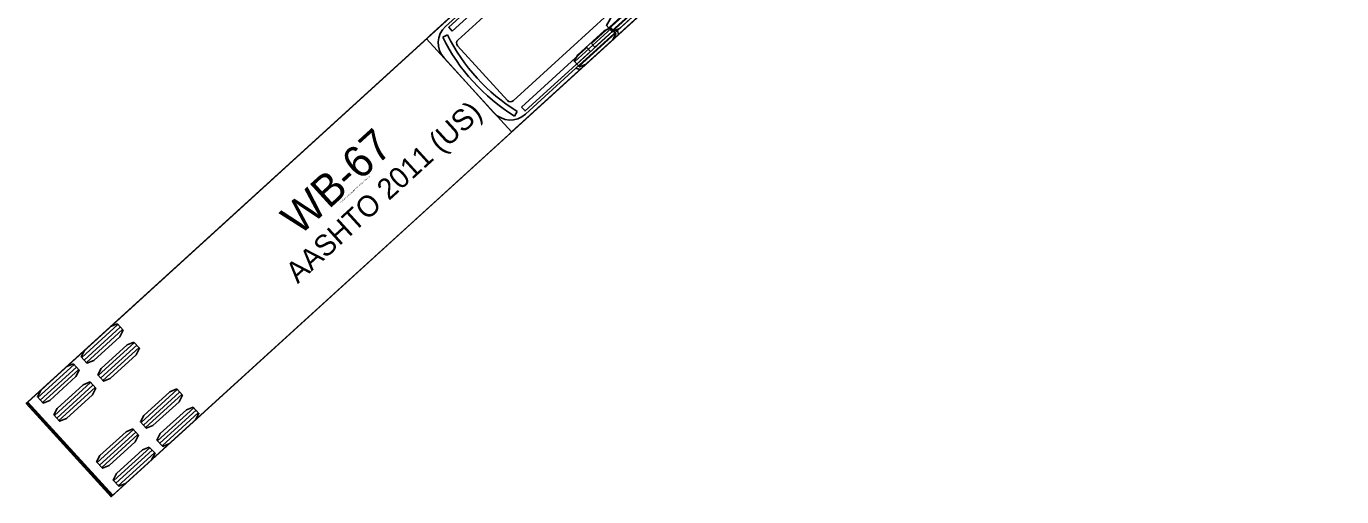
# Model space of a CAD drawing. Extents: x 1639988 to 1641860, y 841974 to 844187.
# Drawn here: x 1639988.4 to 1640077.1, y 843375.5 to 843407.2 of the extents above; entities that cross this region are included whole.
import ezdxf

# ---------------------------------------------------------------- set-up
doc = ezdxf.new("R2010")
doc.units = 0
for name, color, linetype in [('Scratch_Level_1', 7, 'Continuous'), ('Scratch_Level_3', 7, 'Continuous'), ('Scratch_Level_4', 7, 'Continuous'), ('Scratch_Level_5', 7, 'Continuous'), ('Scratch_Level_6', 7, 'Continuous')]:
    doc.layers.add(name, color=color, linetype=linetype)

msp = doc.modelspace()

# ---------------------------------------------------------------- linework, layer by layer
at = {"layer": 'Scratch_Level_1'}
for p, q in [((1640030.453, 843409.562), (1640027.743, 843407.093)), ((1640030.608, 843409.393), (1640027.897, 843406.923)), ((1639994.621, 843387.147), (1639992.182, 843384.925)), ((1639994.776, 843386.978), (1639992.336, 843384.755)), ((1639994.93, 843386.808), (1639992.49, 843384.586)), ((1639995.732, 843385.927), (1639993.293, 843383.705)), ((1639995.887, 843385.758), (1639993.447, 843383.535)), ((1639996.041, 843385.589), (1639993.602, 843383.366)), ((1639991.664, 843384.453), (1639989.225, 843382.231)), ((1639991.819, 843384.284), (1639989.379, 843382.061)), ((1639991.973, 843384.114), (1639989.534, 843381.892)), ((1639992.776, 843383.233), (1639990.336, 843381.011)), ((1639992.93, 843383.064), (1639990.49, 843380.842)), ((1639993.084, 843382.895), (1639990.645, 843380.672)), ((1639998.617, 843382.761), (1639996.178, 843380.539)), ((1639998.771, 843382.592), (1639996.332, 843380.369)), ((1639998.926, 843382.422), (1639996.486, 843380.2)), ((1639994.271, 843375.639), (1639988.547, 843381.923)), ((1639999.728, 843381.541), (1639997.289, 843379.319)), ((1639999.883, 843381.372), (1639997.443, 843379.149)), ((1640000.037, 843381.203), (1639997.598, 843378.98)), ((1639995.66, 843380.067), (1639993.221, 843377.845)), ((1639995.815, 843379.898), (1639993.375, 843377.675)), ((1639995.969, 843379.728), (1639993.53, 843377.506)), ((1639991.178, 843378.93), (1639990.999, 843379.126)), ((1639991.357, 843378.734), (1639991.409, 843378.781)), ((1639996.772, 843378.847), (1639994.332, 843376.625)), ((1639991.714, 843378.341), (1639991.536, 843378.537)), ((1639996.926, 843378.678), (1639994.486, 843376.456)), ((1639997.08, 843378.509), (1639994.641, 843376.286))]:
    msp.add_line(p, q, dxfattribs=at)
for points in [[(1639988.552, 843381.927), (1640075.48, 843461.123), (1640079.453, 843464.719), (1640083.447, 843468.294), (1640087.471, 843471.841), (1640091.525, 843475.35), (1640093.544, 843477.118), (1640095.576, 843478.872), (1640099.681, 843482.333), (1640103.837, 843485.735), (1640108.041, 843489.076), (1640112.291, 843492.356), (1640116.585, 843495.576), (1640120.921, 843498.735), (1640125.299, 843501.833), (1640129.717, 843504.87), (1640134.175, 843507.846), (1640138.671, 843510.76)], [(1640137.628, 843497.624), (1640133.283, 843494.579), (1640128.957, 843491.512), (1640124.652, 843488.422), (1640120.37, 843485.306), (1640116.113, 843482.163), (1640111.883, 843478.991), (1640107.682, 843475.786), (1640103.511, 843472.549), (1640099.37, 843469.276), (1640095.259, 843465.968), (1640091.175, 843462.622), (1640087.115, 843459.239), (1640083.077, 843455.821), (1640079.06, 843452.372), (1640075.061, 843448.895), (1640071.078, 843445.391), (1640067.108, 843441.865), (1640059.196, 843434.757), (1640051.304, 843427.597), (1639994.167, 843375.544), (1639988.442, 843381.828), (1639988.552, 843381.927), (1639988.552, 843381.927)], [(1639994.204, 843375.608), (1639994.218, 843375.592), (1639994.271, 843375.64), (1639998.46, 843379.456), (1640033.345, 843411.238), (1640030.483, 843414.38), (1640027.62, 843417.522), (1639992.736, 843385.739), (1639988.547, 843381.922), (1639988.495, 843381.875), (1639988.51, 843381.859)], [(1639988.526, 843381.841), (1639988.526, 843381.84), (1639990.975, 843379.153), (1639990.999, 843379.126), (1639990.947, 843379.079), (1639990.948, 843379.078), (1639991.128, 843378.88)], [(1639991.182, 843378.925), (1639991.533, 843378.539)], [(1639991.482, 843378.492), (1639991.661, 843378.294), (1639991.663, 843378.294), (1639991.714, 843378.341), (1639991.739, 843378.314), (1639994.187, 843375.627), (1639994.188, 843375.626)]]:
    msp.add_lwpolyline(points, dxfattribs=at)
for points in [[(1640030.261, 843409.773), (1640030.646, 843409.351), (1640030.382, 843408.878), (1640028.431, 843407.1), (1640027.935, 843406.881), (1640027.55, 843407.304), (1640027.814, 843407.777), (1640029.765, 843409.555)], [(1639994.583, 843387.189), (1639994.968, 843386.766), (1639994.743, 843386.328), (1639992.986, 843384.728), (1639992.529, 843384.544), (1639992.143, 843384.967), (1639992.369, 843385.405), (1639994.125, 843387.005)], [(1639995.694, 843385.969), (1639996.079, 843385.547), (1639995.854, 843385.108), (1639994.098, 843383.508), (1639993.64, 843383.324), (1639993.255, 843383.747), (1639993.48, 843384.185), (1639995.237, 843385.786)], [(1639991.626, 843384.495), (1639992.011, 843384.072), (1639991.786, 843383.634), (1639990.029, 843382.034), (1639989.572, 843381.85), (1639989.187, 843382.273), (1639989.412, 843382.711), (1639991.168, 843384.311)], [(1639992.737, 843383.275), (1639993.123, 843382.853), (1639992.897, 843382.414), (1639991.141, 843380.814), (1639990.683, 843380.63), (1639990.298, 843381.053), (1639990.523, 843381.492), (1639992.28, 843383.092)], [(1639998.579, 843382.803), (1639998.964, 843382.38), (1639998.739, 843381.942), (1639996.982, 843380.342), (1639996.525, 843380.158), (1639996.139, 843380.581), (1639996.365, 843381.019), (1639998.121, 843382.619)], [(1639999.69, 843381.583), (1640000.075, 843381.161), (1639999.85, 843380.722), (1639998.093, 843379.122), (1639997.636, 843378.938), (1639997.251, 843379.361), (1639997.476, 843379.799), (1639999.232, 843381.4)], [(1639995.622, 843380.109), (1639996.007, 843379.686), (1639995.782, 843379.248), (1639994.025, 843377.648), (1639993.568, 843377.464), (1639993.183, 843377.887), (1639993.408, 843378.325), (1639995.164, 843379.925)], [(1639996.733, 843378.889), (1639997.118, 843378.467), (1639996.893, 843378.028), (1639995.137, 843376.428), (1639994.679, 843376.244), (1639994.294, 843376.667), (1639994.519, 843377.106), (1639996.276, 843378.706)]]:
    msp.add_lwpolyline(points, close=True, dxfattribs=at)
for centre in [(1639988.492, 843381.827), (1639994.171, 843375.594)]:
    msp.add_circle(centre, 0.0266, dxfattribs=at)
for centre, radius, start, end in [((1639988.492, 843381.827), 0.0363, 61.41319, 22.57454), ((1639991.153, 843378.905), 0.0353, 45.67193, 224.02158), ((1639991.154, 843378.904), 0.0352, 222.36102, 41.36143), ((1639991.508, 843378.515), 0.0352, 43.31007, 222.31048), ((1639991.508, 843378.515), 0.0354, 226.62728, 38.81275), ((1639992.709, 843374.247), 2.022, 42.33575, 43.01951)]:
    msp.add_arc(centre, radius, start, end, dxfattribs=at)
at = {"layer": 'Scratch_Level_3'}
for p, q in [((1640030.453, 843409.562), (1640027.743, 843407.093)), ((1640030.608, 843409.393), (1640027.897, 843406.923)), ((1639994.621, 843387.147), (1639992.182, 843384.925)), ((1639994.776, 843386.978), (1639992.336, 843384.755)), ((1639994.93, 843386.808), (1639992.49, 843384.586)), ((1639995.732, 843385.927), (1639993.293, 843383.705)), ((1639995.887, 843385.758), (1639993.447, 843383.535)), ((1639996.041, 843385.589), (1639993.602, 843383.366)), ((1639991.664, 843384.453), (1639989.225, 843382.231)), ((1639991.819, 843384.284), (1639989.379, 843382.061)), ((1639991.973, 843384.114), (1639989.534, 843381.892)), ((1639992.776, 843383.233), (1639990.336, 843381.011)), ((1639992.93, 843383.064), (1639990.49, 843380.842)), ((1639993.084, 843382.895), (1639990.645, 843380.672)), ((1639998.617, 843382.761), (1639996.178, 843380.539)), ((1639998.771, 843382.592), (1639996.332, 843380.369)), ((1639998.926, 843382.422), (1639996.486, 843380.2)), ((1639994.271, 843375.639), (1639988.547, 843381.923)), ((1639999.728, 843381.541), (1639997.289, 843379.319)), ((1639999.883, 843381.372), (1639997.443, 843379.149)), ((1640000.037, 843381.203), (1639997.598, 843378.98)), ((1639995.66, 843380.067), (1639993.221, 843377.845)), ((1639995.815, 843379.898), (1639993.375, 843377.675)), ((1639995.969, 843379.728), (1639993.53, 843377.506)), ((1639991.178, 843378.93), (1639990.999, 843379.126)), ((1639991.357, 843378.734), (1639991.409, 843378.781)), ((1639996.772, 843378.847), (1639994.332, 843376.625)), ((1639991.714, 843378.341), (1639991.536, 843378.537)), ((1639996.926, 843378.678), (1639994.486, 843376.456)), ((1639997.08, 843378.509), (1639994.641, 843376.286))]:
    msp.add_line(p, q, dxfattribs=at)
for points in [[(1639988.549, 843381.924), (1640075.534, 843461.172), (1640079.512, 843464.772), (1640083.513, 843468.352), (1640087.542, 843471.903), (1640091.604, 843475.42), (1640093.625, 843477.189), (1640095.658, 843478.942), (1640099.765, 843482.403), (1640103.924, 843485.805), (1640108.132, 843489.147), (1640112.386, 843492.429), (1640116.685, 843495.651), (1640121.027, 843498.812), (1640125.411, 843501.911), (1640129.834, 843504.95), (1640134.297, 843507.926), (1640138.798, 843510.841)], [(1640138.602, 843498.073), (1640134.234, 843495.066), (1640129.887, 843492.035), (1640125.564, 843488.978), (1640121.266, 843485.892), (1640116.996, 843482.774), (1640112.756, 843479.624), (1640108.547, 843476.438), (1640104.369, 843473.216), (1640100.224, 843469.955), (1640096.105, 843466.653), (1640092.009, 843463.31), (1640087.938, 843459.929), (1640083.891, 843456.514), (1640079.864, 843453.066), (1640075.856, 843449.59), (1640071.865, 843446.086), (1640067.887, 843442.559), (1640059.961, 843435.448), (1640052.057, 843428.282), (1639994.167, 843375.544), (1639988.442, 843381.828), (1639988.549, 843381.924), (1639988.549, 843381.924)], [(1639994.204, 843375.608), (1639994.218, 843375.592), (1639994.271, 843375.64), (1639998.46, 843379.456), (1640033.345, 843411.238), (1640030.483, 843414.38), (1640027.62, 843417.522), (1639992.736, 843385.739), (1639988.547, 843381.922), (1639988.495, 843381.875), (1639988.51, 843381.859)], [(1639988.526, 843381.841), (1639988.526, 843381.84), (1639990.975, 843379.153), (1639990.999, 843379.126), (1639990.947, 843379.079), (1639990.948, 843379.078), (1639991.128, 843378.88)], [(1639991.182, 843378.925), (1639991.533, 843378.539)], [(1639991.482, 843378.492), (1639991.661, 843378.294), (1639991.663, 843378.294), (1639991.714, 843378.341), (1639991.739, 843378.314), (1639994.187, 843375.627), (1639994.188, 843375.626)]]:
    msp.add_lwpolyline(points, dxfattribs=at)
for points in [[(1640030.261, 843409.773), (1640030.646, 843409.351), (1640030.382, 843408.878), (1640028.431, 843407.1), (1640027.935, 843406.881), (1640027.55, 843407.304), (1640027.814, 843407.777), (1640029.765, 843409.555)], [(1639994.583, 843387.189), (1639994.968, 843386.766), (1639994.743, 843386.328), (1639992.986, 843384.728), (1639992.529, 843384.544), (1639992.143, 843384.967), (1639992.369, 843385.405), (1639994.125, 843387.005)], [(1639995.694, 843385.969), (1639996.079, 843385.547), (1639995.854, 843385.108), (1639994.098, 843383.508), (1639993.64, 843383.324), (1639993.255, 843383.747), (1639993.48, 843384.185), (1639995.237, 843385.786)], [(1639991.626, 843384.495), (1639992.011, 843384.072), (1639991.786, 843383.634), (1639990.029, 843382.034), (1639989.572, 843381.85), (1639989.187, 843382.273), (1639989.412, 843382.711), (1639991.168, 843384.311)], [(1639992.737, 843383.275), (1639993.123, 843382.853), (1639992.897, 843382.414), (1639991.141, 843380.814), (1639990.683, 843380.63), (1639990.298, 843381.053), (1639990.523, 843381.492), (1639992.28, 843383.092)], [(1639998.579, 843382.803), (1639998.964, 843382.38), (1639998.739, 843381.942), (1639996.982, 843380.342), (1639996.525, 843380.158), (1639996.139, 843380.581), (1639996.365, 843381.019), (1639998.121, 843382.619)], [(1639999.69, 843381.583), (1640000.075, 843381.161), (1639999.85, 843380.722), (1639998.093, 843379.122), (1639997.636, 843378.938), (1639997.251, 843379.361), (1639997.476, 843379.799), (1639999.232, 843381.4)], [(1639995.622, 843380.109), (1639996.007, 843379.686), (1639995.782, 843379.248), (1639994.025, 843377.648), (1639993.568, 843377.464), (1639993.183, 843377.887), (1639993.408, 843378.325), (1639995.164, 843379.925)], [(1639996.733, 843378.889), (1639997.118, 843378.467), (1639996.893, 843378.028), (1639995.137, 843376.428), (1639994.679, 843376.244), (1639994.294, 843376.667), (1639994.519, 843377.106), (1639996.276, 843378.706)]]:
    msp.add_lwpolyline(points, close=True, dxfattribs=at)
for centre in [(1639988.492, 843381.827), (1639994.171, 843375.594)]:
    msp.add_circle(centre, 0.0266, dxfattribs=at)
for centre, radius, start, end in [((1639988.492, 843381.827), 0.0363, 61.41319, 22.57454), ((1639991.153, 843378.905), 0.0353, 45.67193, 224.02158), ((1639991.154, 843378.904), 0.0352, 222.36102, 41.36143), ((1639991.508, 843378.515), 0.0352, 43.31007, 222.31048), ((1639991.508, 843378.515), 0.0354, 226.62728, 38.81275), ((1639992.709, 843374.247), 2.022, 42.33575, 43.01951)]:
    msp.add_arc(centre, radius, start, end, dxfattribs=at)
at = {"layer": 'Scratch_Level_4'}
for p, q in [((1640044.461, 843430.861), (1640017.53, 843406.325)), ((1640021.259, 843402.231), (1640048.19, 843426.767)), ((1640027.873, 843407.098), (1640025.409, 843404.853)), ((1640028.292, 843406.975), (1640025.493, 843404.425)), ((1640028.013, 843406.944), (1640025.549, 843404.699)), ((1640028.153, 843406.79), (1640025.689, 843404.545)), ((1640017.512, 843405.943), (1640020.878, 843402.249))]:
    msp.add_line(p, q, dxfattribs=at)
for points in [[(1640015.629, 843406.597), (1640063.06, 843449.817), (1640070.951, 843457.031), (1640078.888, 843464.23), (1640090.806, 843475.083), (1640092.811, 843476.877), (1640094.833, 843478.655), (1640096.869, 843480.416), (1640098.92, 843482.162), (1640100.985, 843483.892), (1640103.064, 843485.606), (1640105.157, 843487.304), (1640107.263, 843488.987), (1640111.513, 843492.306), (1640115.812, 843495.563), (1640120.156, 843498.756), (1640124.538, 843501.882), (1640128.957, 843504.942), (1640133.413, 843507.935), (1640137.905, 843510.864)], [(1640139.344, 843500.335), (1640134.956, 843497.359), (1640130.598, 843494.356), (1640126.277, 843491.318), (1640121.995, 843488.234), (1640117.753, 843485.098), (1640113.548, 843481.908), (1640109.381, 843478.668), (1640105.25, 843475.378), (1640101.155, 843472.039), (1640097.092, 843468.655), (1640093.061, 843465.228), (1640089.058, 843461.761), (1640085.078, 843458.257), (1640081.118, 843454.721), (1640073.228, 843447.575), (1640021.148, 843400.126), (1640015.423, 843406.409), (1640015.629, 843406.597), (1640015.629, 843406.597)], [(1640043.632, 843431.77), (1640041.505, 843429.831), (1640041.111, 843429.813), (1640038.524, 843427.455), (1640038.468, 843427.065), (1640022.906, 843412.886), (1640022.631, 843412.976), (1640020.043, 843410.619), (1640020.107, 843410.336), (1640016.701, 843407.234)], [(1640022.088, 843401.322), (1640025.493, 843404.425), (1640025.768, 843404.335), (1640028.355, 843406.692), (1640028.292, 843406.975), (1640043.855, 843421.153), (1640044.248, 843421.172), (1640046.836, 843423.529), (1640046.891, 843423.919)], [(1640016.511, 843406.517), (1640016.838, 843406.672)], [(1640016.603, 843405.115), (1640019.969, 843401.421)], [(1640021.54, 843401.51), (1640021.356, 843401.199)]]:
    msp.add_lwpolyline(points, dxfattribs=at)
for points in [[(1640017.155, 843406.932), (1640016.922, 843407.187), (1640021.328, 843411.201), (1640021.559, 843410.945)], [(1640026.537, 843406.09), (1640026.769, 843405.835), (1640031.175, 843409.849), (1640030.942, 843410.103)], [(1640027.838, 843407.137), (1640028.188, 843406.752), (1640027.949, 843406.322), (1640026.175, 843404.706), (1640025.724, 843404.507), (1640025.374, 843404.892), (1640025.613, 843405.322), (1640027.388, 843406.938)], [(1640021.829, 843401.801), (1640022.061, 843401.546), (1640026.467, 843405.56), (1640026.234, 843405.814)]]:
    msp.add_lwpolyline(points, close=True, dxfattribs=at)
for centre, radius, start, end in [((1640017.712, 843406.125), 1.5, 132.33575, 222.33575), ((1640028.224, 843412.322), 13.073, 206.36281, 238.30869), ((1640028.224, 843412.322), 12.711, 206.39299, 238.2785), ((1640017.712, 843406.125), 0.27, 132.33575, 222.33575), ((1640021.077, 843402.431), 0.27, 222.33575, 312.33575), ((1640021.077, 843402.431), 1.5, 222.33575, 312.33575)]:
    msp.add_arc(centre, radius, start, end, dxfattribs=at)
at = {"layer": 'Scratch_Level_5'}
for p, q in [((1640044.461, 843430.861), (1640017.53, 843406.325)), ((1640021.259, 843402.231), (1640048.19, 843426.767)), ((1640027.873, 843407.098), (1640025.409, 843404.853)), ((1640028.292, 843406.975), (1640025.493, 843404.425)), ((1640028.013, 843406.944), (1640025.549, 843404.699)), ((1640028.153, 843406.79), (1640025.689, 843404.545)), ((1640017.512, 843405.943), (1640020.878, 843402.249))]:
    msp.add_line(p, q, dxfattribs=at)
for points in [[(1640015.633, 843406.6), (1640063.06, 843449.817), (1640070.951, 843457.031), (1640078.888, 843464.23), (1640090.806, 843475.083), (1640092.811, 843476.877), (1640094.833, 843478.655), (1640096.869, 843480.416), (1640098.92, 843482.162), (1640100.985, 843483.892), (1640103.064, 843485.606), (1640105.157, 843487.304), (1640107.263, 843488.987), (1640111.513, 843492.306), (1640115.812, 843495.563), (1640120.156, 843498.756), (1640124.538, 843501.882), (1640128.957, 843504.942), (1640133.413, 843507.935), (1640137.905, 843510.864)], [(1640139.344, 843500.335), (1640134.956, 843497.359), (1640130.598, 843494.356), (1640126.277, 843491.318), (1640121.995, 843488.234), (1640117.753, 843485.098), (1640113.548, 843481.908), (1640109.381, 843478.668), (1640105.25, 843475.378), (1640101.155, 843472.039), (1640097.092, 843468.655), (1640093.061, 843465.228), (1640089.058, 843461.761), (1640085.078, 843458.257), (1640081.118, 843454.721), (1640073.228, 843447.575), (1640021.148, 843400.126), (1640015.423, 843406.409), (1640015.633, 843406.6), (1640015.633, 843406.6)], [(1640043.632, 843431.77), (1640041.505, 843429.831), (1640041.111, 843429.813), (1640038.524, 843427.455), (1640038.468, 843427.065), (1640022.906, 843412.886), (1640022.631, 843412.976), (1640020.043, 843410.619), (1640020.107, 843410.336), (1640016.701, 843407.234)], [(1640022.088, 843401.322), (1640025.493, 843404.425), (1640025.768, 843404.335), (1640028.355, 843406.692), (1640028.292, 843406.975), (1640043.855, 843421.153), (1640044.248, 843421.172), (1640046.836, 843423.529), (1640046.891, 843423.919)], [(1640016.511, 843406.517), (1640016.838, 843406.672)], [(1640016.603, 843405.115), (1640019.969, 843401.421)], [(1640021.54, 843401.51), (1640021.356, 843401.199)]]:
    msp.add_lwpolyline(points, dxfattribs=at)
for points in [[(1640017.155, 843406.932), (1640016.922, 843407.187), (1640021.328, 843411.201), (1640021.559, 843410.945)], [(1640026.537, 843406.09), (1640026.769, 843405.835), (1640031.175, 843409.849), (1640030.942, 843410.103)], [(1640027.838, 843407.137), (1640028.188, 843406.752), (1640027.949, 843406.322), (1640026.175, 843404.706), (1640025.724, 843404.507), (1640025.374, 843404.892), (1640025.613, 843405.322), (1640027.388, 843406.938)], [(1640021.829, 843401.801), (1640022.061, 843401.546), (1640026.467, 843405.56), (1640026.234, 843405.814)]]:
    msp.add_lwpolyline(points, close=True, dxfattribs=at)
for centre, radius, start, end in [((1640017.712, 843406.125), 1.5, 132.33575, 222.33575), ((1640028.224, 843412.322), 13.073, 206.36281, 238.30869), ((1640028.224, 843412.322), 12.711, 206.39299, 238.2785), ((1640017.712, 843406.125), 0.27, 132.33575, 222.33575), ((1640021.077, 843402.431), 0.27, 222.33575, 312.33575), ((1640021.077, 843402.431), 1.5, 222.33575, 312.33575)]:
    msp.add_arc(centre, radius, start, end, dxfattribs=at)
at = {"layer": 'Scratch_Level_6'}
for p, q in [((1640044.461, 843430.861), (1640017.53, 843406.325)), ((1640021.259, 843402.231), (1640048.19, 843426.767)), ((1640027.873, 843407.098), (1640025.409, 843404.853)), ((1640028.292, 843406.975), (1640025.493, 843404.425)), ((1640028.013, 843406.944), (1640025.549, 843404.699)), ((1640028.153, 843406.79), (1640025.689, 843404.545)), ((1640017.512, 843405.943), (1640020.878, 843402.249))]:
    msp.add_line(p, q, dxfattribs=at)
for points in [[(1640015.614, 843406.583), (1640063.06, 843449.817), (1640070.951, 843457.031), (1640078.888, 843464.23), (1640090.806, 843475.083), (1640092.811, 843476.877), (1640094.833, 843478.655), (1640096.869, 843480.416), (1640098.92, 843482.162), (1640100.985, 843483.892), (1640103.064, 843485.606), (1640105.157, 843487.304), (1640107.263, 843488.987), (1640111.513, 843492.306), (1640115.812, 843495.563), (1640120.156, 843498.756), (1640124.538, 843501.882), (1640128.957, 843504.942), (1640133.413, 843507.935), (1640137.905, 843510.864)], [(1640139.344, 843500.335), (1640134.956, 843497.359), (1640130.598, 843494.356), (1640126.277, 843491.318), (1640121.995, 843488.234), (1640117.753, 843485.098), (1640113.548, 843481.908), (1640109.381, 843478.668), (1640105.25, 843475.378), (1640101.155, 843472.039), (1640097.092, 843468.655), (1640093.061, 843465.228), (1640089.058, 843461.761), (1640085.078, 843458.257), (1640081.118, 843454.721), (1640073.228, 843447.575), (1640021.148, 843400.126), (1640015.423, 843406.409), (1640015.614, 843406.583), (1640015.614, 843406.583)], [(1640043.632, 843431.77), (1640041.505, 843429.831), (1640041.111, 843429.813), (1640038.524, 843427.455), (1640038.468, 843427.065), (1640022.906, 843412.886), (1640022.631, 843412.976), (1640020.043, 843410.619), (1640020.107, 843410.336), (1640016.701, 843407.234)], [(1640022.088, 843401.322), (1640025.493, 843404.425), (1640025.768, 843404.335), (1640028.355, 843406.692), (1640028.292, 843406.975), (1640043.855, 843421.153), (1640044.248, 843421.172), (1640046.836, 843423.529), (1640046.891, 843423.919)], [(1640016.511, 843406.517), (1640016.838, 843406.672)], [(1640016.603, 843405.115), (1640019.969, 843401.421)], [(1640021.54, 843401.51), (1640021.356, 843401.199)]]:
    msp.add_lwpolyline(points, dxfattribs=at)
for points in [[(1640017.155, 843406.932), (1640016.922, 843407.187), (1640021.328, 843411.201), (1640021.559, 843410.945)], [(1640026.537, 843406.09), (1640026.769, 843405.835), (1640031.175, 843409.849), (1640030.942, 843410.103)], [(1640027.838, 843407.137), (1640028.188, 843406.752), (1640027.949, 843406.322), (1640026.175, 843404.706), (1640025.724, 843404.507), (1640025.374, 843404.892), (1640025.613, 843405.322), (1640027.388, 843406.938)], [(1640021.829, 843401.801), (1640022.061, 843401.546), (1640026.467, 843405.56), (1640026.234, 843405.814)]]:
    msp.add_lwpolyline(points, close=True, dxfattribs=at)
for centre, radius, start, end in [((1640017.712, 843406.125), 1.5, 132.33575, 222.33575), ((1640028.224, 843412.322), 13.073, 206.36281, 238.30869), ((1640028.224, 843412.322), 12.711, 206.39299, 238.2785), ((1640017.712, 843406.125), 0.27, 132.33575, 222.33575), ((1640021.077, 843402.431), 0.27, 222.33575, 312.33575), ((1640021.077, 843402.431), 1.5, 222.33575, 312.33575)]:
    msp.add_arc(centre, radius, start, end, dxfattribs=at)

# ---------------------------------------------------------------- texts
at = {"layer": 'Scratch_Level_1'}
for s, height, p in [('AASHTO 2011 (US)', 1.41667, (1640006.738, 843389.863)), ('WB-67', 2.125, (1640006.852, 843393.081)), ('(c) 2019 Transoft Solutions, Inc. All rights reserved.', 0.085, (1640009.642, 843395.335))]:
    msp.add_text(s, height=height, rotation=42.33575, dxfattribs=at).set_placement(p)
at = {"layer": 'Scratch_Level_3'}
for s, height, p in [('AASHTO 2011 (US)', 1.41667, (1640006.738, 843389.863)), ('WB-67', 2.125, (1640006.852, 843393.081)), ('(c) 2019 Transoft Solutions, Inc. All rights reserved.', 0.085, (1640009.642, 843395.335))]:
    msp.add_text(s, height=height, rotation=42.33575, dxfattribs=at).set_placement(p)

doc.saveas('drawing.dxf')
